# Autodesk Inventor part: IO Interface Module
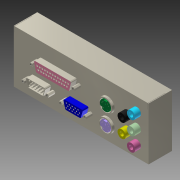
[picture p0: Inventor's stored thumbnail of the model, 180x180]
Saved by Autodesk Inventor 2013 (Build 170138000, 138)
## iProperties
Company: Autodesk Inc.
Created: 2005-12
Part Number: IO Interface Module
Document SubType Name: Modeling
Designer: Autodesk Inc.
Density: 1 g/cm^3
Mass: 106.435 g
Surface Area: 212.581 cm^2
Volume: 106.435 cm^3
Material: Allgemein
Title: Personal Computer
Author: Autodesk Inc.
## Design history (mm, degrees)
sketch "Sketch1"
  geometry: L1 (0, 24)-(0, -4) reference; L2 (-80.5, 0)-(80.5, 0) reference; L3 (-57.5, 0)-(57.5, 0); L4 (57.5, 0)-(57.5, 20); L5 (57.5, 20)-(-57.5, 20); L6 (-57.5, 20)-(-57.5, 0)
  constraints: 8 end point, 2 parallel, 1 horizontal, 1 perpendicular, 1 point on line, 1 other
  dimensions: "d0" = 115 distance of L4.end L5.end; "d1" = 20 distance of L3.end L4.end
extrude "Extrusion1" new body sketch "Sketch1" distance "d2" = 45; taper "d3" = 0 deg
sketch "Sketch3"
  geometry: L1 (57.5, 0)-(-57.5, 0) reference; L2 (57.5, 20)-(57.5, 0) reference; L3 (57, 15)-(56.8, 15); L4 (56.8, 15)-(56.8, 0); L5 (56.8, 0)-(57, 0); L6 (57, 0)-(57, 15)
  constraints: 8 end point, 2 parallel, 1 horizontal, 1 perpendicular, 1 point on line
  dimensions: "d8" = 0.5 distance between parallel lines of L2 L6; "d9" = 0.2 distance of L3.start L3.end; "d10" = 15 distance of L3.end L4.end
extrude "Extrusion3" cut sketch "Sketch3" distance "d11" = 5; taper "d12" = 0 deg
mirror "Mirror1"
split "Split1"
split "Split2"
split "Split3"
sketch "Sketch7" dims "d16" = 25
  geometry: L1 (0, 0)-(115, 0) reference; L2 (115, 30)-(115, 0) reference; L3 (77, 23)-(85, 23); L4 (85, 23)-(85, 6); L5 (85, 6)-(77, 6); L6 (77, 6)-(77, 23); 2 further points
  constraints: 8 end point, 2 horizontal alignment, 2 midpoint, 2 parallel, 1 horizontal, 1 perpendicular, 4 other
  dimensions: "d17" = 8 distance between parallel lines of L6 L4; "d18" = 30 distance between parallel lines of L2 L4; "d19" = 6 distance between parallel lines of L1 L5
extrude "Extrusion4" join sketch "Sketch7" distance "d20" = 0.5; taper "d21" = 0 deg
fillet "Fillet1" dims "d22" = 0.25
pattern_linear "Rectangular Pattern1" dims "d25" = 15
sketch "Sketch8"
  geometry: L1 (-0.7, -45)-(114.3, -45) reference; L2 (114.3, -45)-(114.3, 0) reference; L3 (0, -5)-(-0.2, -5) reference; L4 (104.3, -10.132)-(104.3, -39.449); L5 (96.3, -15.285)-(96.3, -32.921); C1 r 3.5 at (104.3, -35); C2 r 1.75 at (104.3, -35); C3 r 3.5 at (104.3, -23); C4 r 1.75 at (104.3, -23); C5 r 3.5 at (104.3, -11); C6 r 1.75 at (104.3, -11); C7 r 1.75 at (96.3, -17); C8 r 3.5 at (96.3, -17); C9 r 1.75 at (96.3, -29); C10 r 3.5 at (96.3, -29)
  constraints: 10 centre point, 8 equal radius, 5 coincident, 5 point on line, 4 end point, 1 parallel, 1 perpendicular
  dimensions: "d26" = 3.5 diameter of C2; "d27" = 7 diameter of C1; "d28" = 10 distance between parallel lines of L2 L4; "d29" = 10 distance from line of L1 C1.centre; "d30" = 12 distance of C3.centre C1.centre; "d31" = 12 distance of C3.centre C5.centre; "d32" = 8 distance between parallel lines of L4 L5; "d33" = 12 distance of C9.centre C7.centre; "d34" = 16 distance from line of L1 C10.centre
extrude "Extrusion5" join sketch "Sketch8" distance "d35" = 5; taper "d36" = 0 deg
sketch "Sketch9"
  geometry: L1 (-0.7, -45)-(114.3, -45) reference; L2 (114.3, -45)-(114.3, 0) reference; L3 (0, -5)-(-0.2, -5) reference; L4 (79.3, -18)-(79.3, -33); C1 r 6 at (79.3, -18); C2 r 6 at (79.3, -33)
  constraints: 2 centre point, 2 end point, 1 equal radius, 1 perpendicular
  dimensions: "d37" = 35 distance between parallel lines of L2 L4; "d38" = 12 diameter of C2; "d39" = 15 distance of L4.end L4.start; "d40" = 12 distance from line of L1 L4.end
extrude "Extrusion6" join sketch "Sketch9" distance "d41" = 2; taper "d42" = 0 deg
sketch "Sketch10"
  geometry: L1 (-4.031, -2)-(-2.531, -2); L2 (-2.531, -2)-(-2.531, -3.721); L3 (4.031, -2)-(2.531, -2); L4 (2.531, -2)-(2.531, -3.721); L5 (0, 0)-(0, 4.5); L6 (-1.5, 4.243)-(-1.5, 3.243); L7 (-1.5, 3.243)-(1.5, 3.243); L8 (1.5, 3.243)-(1.5, 4.243); C1 r 6 at (0, 0) reference; C2 r 5 at (0, 0); A1 r 4.5 centre (0, 0) between (-1.5, 4.243) and (-4.031, -2); A2 r 4.5 centre (0, 0) between (-2.531, -3.721) and (2.531, -3.721); A3 r 4.5 centre (0, 0) between (4.031, -2) and (1.5, 4.243)
  constraints: 16 end point, 6 point on circle, 4 centre point, 4 perpendicular, 3 parallel, 2 coincident, 2 equal length, 1 horizontal, 1 other
  dimensions: "d44" = 2 distance from line of L1 C1.centre; "d45" = 1.5 distance of L1.start L1.end; "d46" = 3 distance of L6.end L7.end; "d47" = 1 distance of L7.end L8.end; "d48" = 10 diameter of C2
extrude "Extrusion7" cut sketch "Sketch10" distance "d49" = 5; taper "d50" = 0 deg
sketch "Sketch11"
  geometry: L1 (75.269, -20)-(76.769, -20) reference; L2 (79.3, -18)-(79.3, -16.324); L3 (79, -15.5)-(79.6, -15.5); L4 (79.6, -15.5)-(79.6, -17.5); L5 (79.6, -17.5)-(79, -17.5); L6 (79, -17.5)-(79, -15.5); C1 r 0.25 at (77.26, -15.8); C2 r 0.25 at (76.472, -17); C3 r 0.25 at (81.34, -15.8); C4 r 0.25 at (82.128, -17); C5 r 0.25 at (77.642, -20.5); C6 r 0.25 at (80.958, -20.5); A1 r 4.5 centre (79.3, -18) between (76.769, -21.721) and (81.831, -21.721) reference; A2 r 4.5 centre (79.3, -18) between (77.8, -13.757) and (75.269, -20) reference; A3 r 3 centre (79.3, -18) between (77.26, -15.8) and (76.472, -17)
  constraints: 10 end point, 7 centre point, 6 point on circle, 5 equal radius, 3 symmetric about line, 2 parallel, 2 perpendicular, 1 coincident, 1 horizontal, 1 other
  dimensions: "d51" = 6 diameter of A3; "d52" = 0.5 diameter of C1; "d53" = 1 vertical distance of A1.centre C2.centre; "d54" = 2.2 vertical distance of A1.centre C1.centre; "d55" = 2.5 vertical distance of C5.centre A1.centre; "d56" = 2 distance of L5.end L3.start; "d57" = 0.5 distance from line of A1.centre L5; "d58" = 0.6 distance of L3.start L3.end
extrude "Extrusion8" cut sketch "Sketch11" distance "d59" = 3; taper "d60" = 0 deg
pattern_linear "Rectangular Pattern2" dims "d63" = 15
sketch "Sketch12"
  geometry: L1 (-0.7, -45)-(-0.7, 0) reference; L2 (-0.7, -45)-(114.3, -45) reference; L3 (113.6, 0)-(0, 0) reference; L4 (0, -5)-(-0.2, -5) reference; L5 (46.3, -28)-(63.3, -28); L6 (63.3, -28)-(61.3, -35); L7 (61.3, -35)-(48.3, -35); L8 (48.3, -35)-(46.3, -28); L9 (14.3, -28)-(31.3, -28); L10 (31.3, -28)-(29.3, -35); L11 (29.3, -35)-(16.3, -35); L12 (16.3, -35)-(14.3, -28); L13 (21.3, -12)-(53.3, -12); L14 (53.3, -12)-(51.3, -20); L15 (51.3, -20)-(23.3, -20); L16 (23.3, -20)-(21.3, -12)
  constraints: 24 end point, 8 parallel, 3 equal length, 2 collinear
  dimensions: "d64" = 7 distance between parallel lines of L11 L9; "d65" = 17 distance of L9.start L9.end; "d66" = 13 distance of L10.end L11.end; "d67" = 32 distance of L13.start L13.end; "d68" = 28 distance of L14.end L15.end; "d69" = 10 distance between parallel lines of L2 L11; "d70" = 15 distance from line of L1 L9.start; "d71" = 15 distance of L5.start L9.end; "d72" = 12 distance between parallel lines of L13 L3; "d73" = 8 distance between parallel lines of L13 L15; "d74" = 22 distance from line of L1 L13.start
extrude "Extrusion9" join sketch "Sketch12" distance "d75" = 5; taper "d76" = 0 deg
fillet "Fillet2" dims "d77" = 1, "d78" = 1
sketch "Sketch16"
  geometry: L1 (47.626, -28)-(61.974, -28) reference; L2 (60.546, -35)-(49.054, -35) reference; L3 (54.8, -28)-(54.8, -35); L4 (54.8, -31.5)-(57.672, -31.5); L5 (54.8, -29.75)-(60.918, -29.75); L6 (54.8, -31.5)-(46.021, -31.5); L7 (57.8, -31.5)-(59.05, -29.75); L8 (60.3, -31.5)-(59.05, -29.75); C1 r 0.5 at (55.3, -31.5); C2 r 0.5 at (57.8, -31.5); C3 r 0.5 at (60.3, -31.5); C4 r 0.5 at (52.8, -31.5); C5 r 0.5 at (50.3, -31.5); C6 r 0.5 at (59.05, -29.75); C7 r 0.5 at (56.55, -29.75); C8 r 0.5 at (54.05, -29.75); C9 r 0.5 at (51.55, -29.75); C10 r 0.5 at (49.05, -29.75); C11 r 0.5 at (56.55, -33.25); C12 r 0.5 at (59.05, -33.25); C13 r 0.5 at (54.05, -33.25); C14 r 0.5 at (51.55, -33.25); C15 r 0.5 at (49.05, -33.25); 2 further points
  constraints: 15 centre point, 12 end point, 11 point on line, 9 equal radius, 7 symmetric about line, 3 midpoint, 2 coincident, 2 parallel, 1 equal length, 1 perpendicular, 5 other
  dimensions: "d85" = 1.75 distance between parallel lines of L5 L1; "d86" = 1 diameter of C5; "d87" = 2.5 distance of C4.centre C5.centre; "d88" = 2.5 distance of C1.centre C4.centre (= d87); "d89" = 2.5 distance of L7.start C1.centre (= d88); "d90" = 2.5 distance of L8.start L7.start (= d89); "d91" = 2 distance from line of L3 C4.centre; "d92" = 2.5 distance of L7.end C7.centre (= d90); "d93" = 2.5 distance of C7.centre C8.centre (= d92); "d94" = 2.5 distance of C8.centre C9.centre (= d93); "d95" = 2.5 distance of C9.centre C10.centre (= d94)
extrude "Extrusion11" cut sketch "Sketch16" distance "d96" = 5; taper "d97" = 0 deg
sketch "Sketch17"
  geometry: L1 (30.936, -29.275)-(29.507, -34.275) reference; L2 (15.626, -28)-(29.974, -28) reference; L3 (16.093, -34.275)-(14.664, -29.275) reference; L4 (28.546, -35)-(17.054, -35) reference; L5 (22.8, -28)-(22.8, -35); L6 (22.8, -31.5)-(25.778, -31.5); L7 (17.567, -29.75)-(27.661, -29.75); L8 (22.8, -31.5)-(14.443, -31.5); L9 (25.8, -31.5)-(27.05, -29.75); L10 (28.3, -31.5)-(27.05, -29.75); L11 (17.567, -33.25)-(27.661, -33.25); L12 (30.455, -29.137)-(29.026, -34.137); L13 (28.546, -34.5)-(17.054, -34.5); L14 (16.574, -34.137)-(15.145, -29.137); L15 (15.626, -28.5)-(29.974, -28.5); C1 r 0.5 at (23.3, -31.5); C2 r 0.5 at (20.8, -31.5); C3 r 0.5 at (18.3, -31.5); C4 r 0.5 at (25.8, -31.5); C5 r 0.5 at (28.3, -31.5); C6 r 0.5 at (27.05, -29.75); C7 r 0.5 at (24.55, -29.75); C8 r 0.5 at (22.05, -29.75); C9 r 0.5 at (19.55, -29.75); C10 r 0.5 at (17.05, -29.75); C11 r 0.5 at (22.05, -33.25); C12 r 0.5 at (17.05, -33.25); C13 r 0.5 at (19.55, -33.25); C14 r 0.5 at (24.55, -33.25); C15 r 0.5 at (27.05, -33.25); A1 r 1 centre (28.546, -34) between (28.546, -35) and (29.507, -34.275) reference; A2 r 1 centre (29.974, -29) between (30.936, -29.275) and (29.974, -28) reference; A3 r 1 centre (15.626, -29) between (15.626, -28) and (14.664, -29.275) reference; A4 r 1 centre (17.054, -34) between (16.093, -34.275) and (17.054, -35) reference; A5 r 0.5 centre (29.974, -29) between (30.455, -29.137) and (29.974, -28.5); A6 r 0.5 centre (28.546, -34) between (28.546, -34.5) and (29.026, -34.137); A7 r 0.5 centre (17.054, -34) between (16.574, -34.137) and (17.054, -34.5); A8 r 0.5 centre (15.626, -29) between (15.626, -28.5) and (15.145, -29.137); 1 further point
  constraints: 22 end point, 19 centre point, 15 point on line, 9 equal radius, 8 point on circle, 8 symmetric about line, 3 midpoint, 2 coincident, 2 parallel, 1 equal length, 1 perpendicular, 12 other
  dimensions: "d98" = 1.75 distance between parallel lines of L7 L2; "d99" = 2.5 distance of C2.centre C3.centre; "d100" = 2.5 distance of C1.centre C2.centre (= d99); "d101" = 2.5 distance of L9.start C1.centre (= d100); "d102" = 2.5 distance of L10.start L9.start (= d101); "d103" = 2 distance from line of L5 C2.centre; "d104" = 1 diameter of C3; "d105" = 2.5 distance of L9.end C7.centre (= d102); "d106" = 2.5 distance of C7.centre C8.centre (= d105); "d107" = 2.5 distance of C8.centre C9.centre (= d106); "d108" = 2.5 distance of C9.centre C10.centre (= d107); "d109" = 0.5 distance between parallel lines of L2 L15
extrude "Extrusion12" cut sketch "Sketch17" distance "d110" = 5; taper "d111" = 0 deg
fillet "Fillet3" dims "d112" = 0.5
sketch "Sketch18" dims "d114" = 2.66667 (= d113)
  geometry: L1 (22.581, -12)-(52.019, -12) reference; L2 (50.519, -20)-(24.081, -20) reference; L3 (37.3, -12)-(37.3, -20); L4 (24.1, -14.667)-(25.2, -17.333); L5 (26.3, -14.667)-(25.2, -17.333); C1 r 0.75 at (37.3, -14.667); C2 r 0.75 at (35.1, -14.667); C3 r 0.75 at (32.9, -14.667); C4 r 0.75 at (30.7, -14.667); C5 r 0.75 at (28.5, -14.667); C6 r 0.75 at (26.3, -14.667); C7 r 0.75 at (24.1, -14.667); C8 r 0.75 at (39.5, -14.667); C9 r 0.75 at (41.7, -14.667); C10 r 0.75 at (43.9, -14.667); C11 r 0.75 at (46.1, -14.667); C12 r 0.75 at (48.3, -14.667); C13 r 0.75 at (50.5, -14.667); C14 r 0.75 at (25.2, -17.333); C15 r 0.75 at (27.4, -17.333); C16 r 0.75 at (29.6, -17.333); C17 r 0.75 at (31.8, -17.333); C18 r 0.75 at (34, -17.333); C19 r 0.75 at (36.2, -17.333); C20 r 0.75 at (38.4, -17.333); C21 r 0.75 at (40.6, -17.333); C22 r 0.75 at (42.8, -17.333); C23 r 0.75 at (45, -17.333); C24 r 0.75 at (47.2, -17.333); C25 r 0.75 at (49.4, -17.333); 3 further points
  constraints: 25 centre point, 24 equal radius, 8 symmetric about line, 6 end point, 4 coincident, 2 midpoint, 1 equal length, 1 point on line, 1 vertical, 27 other
  dimensions: "d113" = 2.66667 dimension on L1; "d115" = 2.2 distance of C1.centre C2.centre; "d116" = 2.2 distance of C2.centre C3.centre (= d115); "d117" = 2.2 distance of C3.centre C4.centre (= d116); "d118" = 2.2 distance of C4.centre C5.centre (= d117); "d119" = 2.2 distance of C5.centre L5.start (= d118); "d120" = 2.2 distance of L5.start point (24.1, -14.667) (= d119); "d121" = 1.5 diameter of C7; "d122" = 2.2 distance of C15.centre L4.end (= d119); "d123" = 2.2 distance of C16.centre C15.centre (= d122); "d124" = 2.2 distance of C17.centre C16.centre (= d123); "d125" = 2.2 distance of C18.centre C17.centre (= d124); "d126" = 2.2 distance of C19.centre C18.centre (= d125); "d127" = 2.2 distance of C20.centre C19.centre (= d126); "d128" = 2.2 distance of C21.centre C20.centre (= d127); "d129" = 2.2 distance of C22.centre C21.centre (= d128); "d130" = 2.2 distance of C23.centre C22.centre (= d128); "d131" = 2.2 distance of C24.centre C23.centre (= d128)
extrude "Extrusion13" cut sketch "Sketch18" distance "d132" = 5; taper "d133" = 0 deg
sketch "Sketch19"
  geometry: L1 (62.936, -29.275)-(61.507, -34.275) reference; L2 (48.093, -34.275)-(46.664, -29.275) reference; L3 (30.936, -29.275)-(29.507, -34.275) reference; L4 (16.093, -34.275)-(14.664, -29.275) reference; L5 (15.626, -28)-(29.974, -28) reference; L6 (52.989, -13.243)-(51.489, -19.243) reference; L7 (23.111, -19.243)-(21.611, -13.243) reference; L8 (22.581, -12)-(52.019, -12) reference; L9 (113.6, 0)-(0, 0) reference; L10 (14.219, -16)-(57.884, -16); L11 (12.39, -30.501)-(13.714, -31.204); L12 (13.714, -31.204)-(13.768, -32.703); L13 (13.768, -32.703)-(12.496, -33.499); L14 (12.496, -33.499)-(11.171, -32.796); L15 (11.171, -32.796)-(11.118, -31.297); L16 (11.118, -31.297)-(12.39, -30.501); L17 (33.623, -30.574)-(34.625, -31.69); L18 (34.625, -31.69)-(34.159, -33.116); L19 (34.159, -33.116)-(32.692, -33.426); L20 (32.692, -33.426)-(31.689, -32.31); L21 (31.689, -32.31)-(32.155, -30.884); L22 (32.155, -30.884)-(33.623, -30.574); L23 (43.275, -31.059)-(44.674, -30.518); L24 (44.674, -30.518)-(45.842, -31.459); L25 (45.842, -31.459)-(45.611, -32.941); L26 (45.611, -32.941)-(44.212, -33.482); L27 (44.212, -33.482)-(43.044, -32.541); L28 (43.044, -32.541)-(43.275, -31.059); L29 (65.162, -30.5)-(66.458, -31.254); L30 (66.458, -31.254)-(66.454, -32.754); L31 (66.454, -32.754)-(65.153, -33.5); L32 (65.153, -33.5)-(63.856, -32.746); L33 (63.856, -32.746)-(63.86, -31.246); L34 (63.86, -31.246)-(65.162, -30.5); L35 (19.75, -17.431)-(18.286, -17.106); L36 (18.286, -17.106)-(17.836, -15.675); L37 (17.836, -15.675)-(18.85, -14.569); L38 (18.85, -14.569)-(20.314, -14.894); L39 (20.314, -14.894)-(20.764, -16.325); L40 (20.764, -16.325)-(19.75, -17.431); L41 (56.561, -16.812)-(55.228, -17.498); L42 (55.228, -17.498)-(53.966, -16.686); L43 (53.966, -16.686)-(54.039, -15.188); L44 (54.039, -15.188)-(55.372, -14.502); L45 (55.372, -14.502)-(56.634, -15.314); L46 (56.634, -15.314)-(56.561, -16.812); 14 further points
  constraints: 74 end point, 10 point on line, 5 equal length, 2 horizontal, 77 other
  dimensions: "d134" = 4 dimension on L5; "d135" = 4 distance between parallel lines of L10 L8; "d136" = 1.5 distance of L15.end L11.start; "d137" = 3 distance of point (15.443, -32) point (12.443, -32); "d138" = 3 distance of point (33.157, -32) point (30.157, -32) (= d137); "d139" = 3 distance of point (47.443, -32) point (44.443, -32) (= d138); "d140" = 3 distance of point (62.157, -32) point (65.157, -32) (= d139); "d141" = 3 distance of point (55.3, -16) point (52.3, -16) (= d140); "d142" = 3 distance of point (22.3, -16) point (19.3, -16) (= d137)
extrude "Extrusion14" join sketch "Sketch19" distance "d143" = 5.5; taper "d144" = 0 deg
sketch "Sketch20"
  geometry: L1 (18.286, -17.106)-(17.836, -15.675) reference; L2 (20.314, -14.894)-(20.764, -16.325) reference; L3 (13.714, -31.204)-(13.768, -32.703) reference; L4 (12.39, -30.501)-(13.714, -31.204) reference; L5 (11.118, -31.297)-(12.39, -30.501) reference; L6 (11.171, -32.796)-(11.118, -31.297) reference; L7 (12.496, -33.499)-(11.171, -32.796) reference; L8 (13.768, -32.703)-(12.496, -33.499) reference; L9 (34.625, -31.69)-(34.159, -33.116) reference; L10 (33.623, -30.574)-(34.625, -31.69) reference; L11 (32.155, -30.884)-(33.623, -30.574) reference; L12 (31.689, -32.31)-(32.155, -30.884) reference; L13 (32.692, -33.426)-(31.689, -32.31) reference; L14 (34.159, -33.116)-(32.692, -33.426) reference; L15 (44.674, -30.518)-(45.842, -31.459) reference; L16 (43.275, -31.059)-(44.674, -30.518) reference; L17 (43.044, -32.541)-(43.275, -31.059) reference; L18 (44.212, -33.482)-(43.044, -32.541) reference; L19 (45.611, -32.941)-(44.212, -33.482) reference; L20 (45.842, -31.459)-(45.611, -32.941) reference; L21 (55.228, -17.498)-(53.966, -16.686) reference; L22 (56.561, -16.812)-(55.228, -17.498) reference; L23 (56.634, -15.314)-(56.561, -16.812) reference; L24 (55.372, -14.502)-(56.634, -15.314) reference; L25 (54.039, -15.188)-(55.372, -14.502) reference; L26 (53.966, -16.686)-(54.039, -15.188) reference; L27 (66.458, -31.254)-(66.454, -32.754) reference; L28 (65.162, -30.5)-(66.458, -31.254) reference; L29 (63.86, -31.246)-(65.162, -30.5) reference; L30 (63.856, -32.746)-(63.86, -31.246) reference; L31 (65.153, -33.5)-(63.856, -32.746) reference; L32 (66.454, -32.754)-(65.153, -33.5) reference; L33 (18.85, -14.569)-(19.75, -17.431); L34 (18.061, -16.39)-(20.539, -15.61); L35 (55.372, -14.502)-(55.228, -17.498); L36 (54.002, -15.937)-(56.598, -16.063); L37 (12.39, -30.501)-(12.496, -33.499); L38 (11.145, -32.046)-(13.741, -31.954); L39 (33.623, -30.574)-(32.692, -33.426); L40 (31.922, -31.597)-(34.392, -32.403); L41 (44.674, -30.518)-(44.212, -33.482); L42 (43.159, -31.8)-(45.726, -32.2); L43 (65.162, -30.5)-(65.153, -33.5); L44 (63.858, -31.996)-(66.456, -32.004); 6 further points
  constraints: 24 end point, 18 midpoint, 5 parallel
hole "Hole1" sketch "Sketch20" diameter "d145" = 1.583; stored, may be unused: countersink angle "d149" = 90 deg, drill point angle "d151" = 0 deg; dims "d146" = 6, "d147" = 4, "d148" = 2, "d150" = 4
body "Solid1"
sketch "Sketch4"
  geometry: L1 (57.5, 20)-(57.5, 0) reference; L2 (57, 15)-(57.5, 15)
  constraints: 2 end point, 1 perpendicular, 1 point on line
sketch "Sketch5"
  geometry: L1 (-45, 20)-(-45, 15) reference; L2 (0, 20)-(-45, 20) reference; L3 (-45, 15)-(-25, 15); L4 (-25, 15)-(-15, 18); L5 (-15, 18)-(-15, 20)
  constraints: 6 end point, 1 parallel, 1 perpendicular, 1 point on line
  dimensions: "d13" = 30 distance between parallel lines of L1 L5; "d14" = 2 distance of L4.end L5.end; "d15" = 20 distance of L1.end L3.end
sketch "Sketch6"
  geometry: L1 (0, -15)-(0, -45) reference; L2 (115, -15)-(0, -15)
  constraints: 2 end point, 1 perpendicular
node "Projected Loop1"
node "Projected Loop2"
node "Projected Loop3"
node "Projected Loop4"
node "Projected Loop5"
other parameters: "d43" = 9
